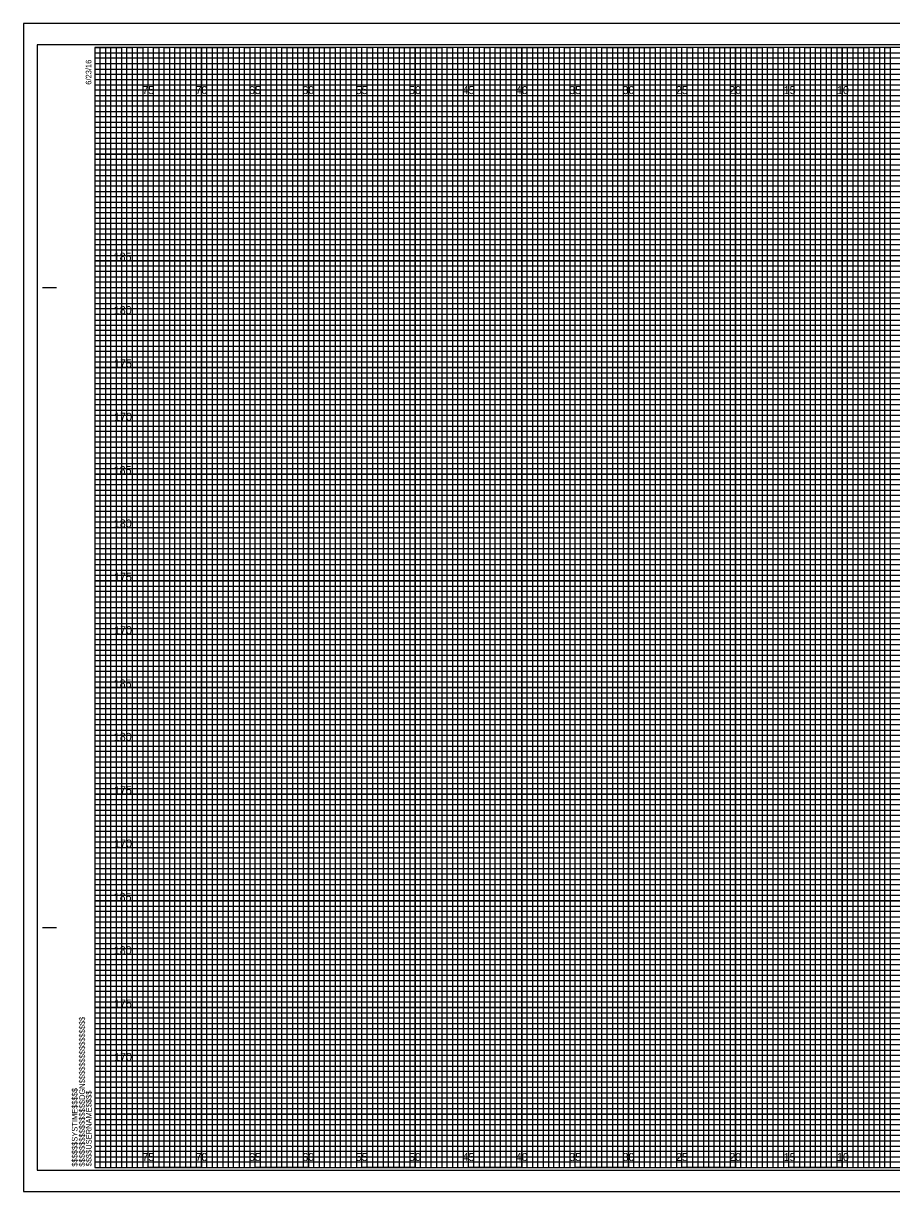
# Model space of a CAD drawing. Extents: x -7 to 162, y -2 to 767.
# Drawn here: x -6.7 to 74.6, y 217.8 to 327.2 of the extents above; entities that cross this region are included whole.
import ezdxf

# ---------------------------------------------------------------- set-up
doc = ezdxf.new("R2010")
doc.units = 0
for name, color, linetype in [('Exist Cross Section Cell', 7, 'Continuous'), ('Prop CMT Pvmt Course 1', 7, 'Continuous'), ('Prop CMT Pvmt Course 1 Wedge', 7, 'Continuous'), ('Prop CMT Pvmt Course 2', 7, 'Continuous'), ('Prop CMT Pvmt Course 3', 7, 'Continuous'), ('Prop CMT Pvmt Surface Shoulder', 7, 'Continuous'), ('Prop CMT Shld Paved Course 2', 7, 'Continuous'), ('Prop CMT Shld Paved Course 3', 7, 'Continuous'), ('Prop CMT Slope Grass', 7, 'Continuous'), ('Prop CMT Subgrade Earthwork', 7, 'Continuous'), ('Scratch_Level_0', 7, 'Continuous')]:
    doc.layers.add(name, color=color, linetype=linetype)

msp = doc.modelspace()

# ---------------------------------------------------------------- linework, layer by layer
at = {"layer": 'Prop CMT Pvmt Course 1'}
for p, q in [((0, 324.5), (130, 324.5)), ((130, 323.99), (0, 323.99)), ((0, 323.99), (0, 323.5)), ((0, 323.5), (130, 323.5)), ((130, 322.94), (0, 322.94)), ((0, 322.94), (0, 322)), ((0, 322), (160, 322))]:
    msp.add_line(p, q, dxfattribs=at)
for points in [[(0, 321.5), (135, 321.5), (160, 321.5), (160, 321), (0, 321)], [(0, 320.5), (160, 320.5), (160, 319.5), (0, 319.5)], [(0, 319), (160, 319), (160, 318.5), (0, 318.49)], [(0, 318), (160, 318), (160, 317), (0, 317)], [(0, 316.5), (160, 316.5), (160, 316), (0, 316)], [(0, 315.5), (160, 315.5), (160, 314.5), (0, 314.5)], [(0, 314), (160, 314), (160, 313.5), (0, 313.5)], [(0, 313), (160, 313), (160, 312), (0, 312)], [(0, 311.5), (160, 311.5), (160, 311), (0, 311)], [(0, 310.5), (160, 310.5), (160, 309.5), (0, 309.5)], [(0, 309), (160, 309), (160, 308.5), (0, 308.5)], [(0, 308), (160, 308), (160, 306.98), (160, 306.5), (160, 306), (0, 306)], [(0, 307), (160, 307), (160, 306.5), (0, 306.5)], [(0, 305.5), (160, 305.5), (160, 304.5), (0, 304.51)], [(0, 304.51), (160, 304.5), (160, 304), (0, 304)], [(0, 303.5), (160, 303.5), (160, 303), (0, 303)], [(0, 302), (160, 302), (160, 301.5), (0, 301.5)], [(0, 301), (160, 301), (160, 300.5), (0, 300.5)], [(-0.04, 299.44), (160, 299.44), (160, 298.94), (-0.04, 298.94)], [(0, 298.5), (160, 298.5), (160, 298), (0, 298)], [(0, 297), (160, 297), (160, 296.5), (0, 296.5)], [(0, 296), (160, 296), (160, 295.5), (0, 295.5)], [(0, 294.5), (160, 294.5), (160, 294), (0, 294)], [(0, 293.5), (160, 293.5), (160, 293), (0, 293)], [(0, 292), (160, 292), (160, 291.5), (0, 291.5)], [(0, 291), (160, 291), (160, 290.5), (0, 290.5)], [(0, 289.5), (160, 289.5), (160, 288.99), (0, 289)], [(0, 288.5), (160, 288.5), (160, 288), (0, 288)], [(0, 287), (160, 287), (160, 286.5), (0, 286.5)], [(0, 286), (160, 286), (160, 285.5), (0, 285.5)], [(0, 284.5), (160, 284.5), (160, 284), (0, 284)], [(0, 283.5), (160, 283.5), (160, 283), (0, 283)], [(0, 282), (160, 282), (160, 281.5), (0, 281.5)], [(0, 281), (160, 281), (160, 280.5), (0, 280.5)], [(0, 279.5), (160, 279.5), (160, 279), (0, 279)], [(0, 278.5), (160.03, 278.45), (160, 278), (0, 278)], [(0, 277), (160, 277), (160, 276.5), (0, 276.5)], [(0, 276), (160, 276), (160, 275.5), (0, 275.5)], [(0, 274.5), (160, 274.5), (160, 274), (0, 274)], [(0, 273.5), (160, 273.5), (160, 273), (0, 273)], [(0, 272), (160, 272), (160, 271.5), (0, 271.5)], [(0, 271), (160, 271), (160, 270.5), (0, 270.5)], [(0, 269.5), (160, 269.5), (160, 269), (0, 269)], [(0, 268.5), (160, 268.5), (160, 268), (0, 268)], [(0, 267), (160, 267), (160, 266.5), (0, 266.5)], [(0, 266), (160, 266), (160, 265.5), (0, 265.5)], [(0, 264.5), (160, 264.5), (160, 264), (0, 264)], [(0, 263.5), (160, 263.5), (160, 263), (0, 263)], [(0, 262), (160, 262), (160, 261.5), (0, 261.5)], [(0, 261), (160, 261), (160, 260.5), (0, 260.5)], [(0, 259.5), (160, 259.5), (160, 258.99), (0, 259)], [(0, 258.5), (160, 258.5), (160, 258), (0, 258)], [(0, 257), (160, 257), (160, 256.5), (0, 256.5)], [(0, 256), (160, 256), (160, 255.5), (0, 255.5)], [(0, 254.5), (160, 254.5), (160, 254), (0, 254)], [(0, 253.5), (160, 253.5), (160, 253), (0, 253)], [(0, 252), (160, 252), (160, 251.5), (0, 251.5)], [(0, 251), (160, 251), (160, 250.5), (0, 250.5)], [(0, 249.5), (160, 249.5), (160, 249), (0, 249)], [(0, 248.5), (160.03, 248.46), (160, 248), (0, 248)], [(0, 247), (160, 247), (160, 246.5), (0, 246.5)], [(0, 246), (160, 246), (160, 245.5), (0, 245.5)], [(0, 244.5), (160, 244.5), (160, 244), (0, 244)], [(0, 243.5), (160, 243.5), (160, 243), (0, 243)], [(0, 242), (160, 242), (160, 241.5), (0, 241.5)], [(0, 241), (160, 241), (160, 240.5), (0, 240.5)], [(0, 239.5), (160, 239.5), (160, 239), (0, 239)], [(0, 238.5), (160, 238.5), (160, 238), (0, 238)], [(0, 237), (160, 237), (160, 236.5), (0, 236.5)], [(0, 236), (160, 236), (160, 235.5), (0, 235.5)], [(0, 234.5), (160, 234.5), (160, 234), (0, 234)], [(0, 233.5), (160, 233.5), (160, 233), (0, 233)], [(0, 232), (160, 232), (160, 231.5), (0, 231.5)], [(0, 231), (160, 231), (160, 230.5), (0, 230.5)], [(0, 229.5), (160, 229.5), (160, 229), (0, 229)], [(0, 228.5), (160, 228.5), (160, 228), (0, 228)], [(0, 227), (160, 227), (160, 226.5), (0, 226.5)], [(0, 226), (160, 226), (160, 225.5), (0, 225.5)], [(0, 224.5), (160, 224.5), (160, 224), (0, 224)], [(0, 223.5), (160, 223.5), (160, 223), (0, 223)], [(0, 222), (160, 222), (160, 221.5), (0, 221.5)], [(0, 221), (160, 221), (160, 220.5), (0, 220.5)]]:
    msp.add_lwpolyline(points, dxfattribs=at)
at = {"layer": 'Prop CMT Pvmt Course 2'}
for p, q in [((5, 220), (5, 325)), ((10, 220), (10, 325)), ((15, 220), (15, 325)), ((20, 220), (20, 325)), ((25, 220), (25, 325)), ((30, 220), (30, 325)), ((35, 220), (35, 325)), ((40, 220), (40, 325)), ((45, 220), (45, 325)), ((50, 220), (50, 325)), ((55, 220), (55, 325)), ((60, 220), (60, 325)), ((65, 220), (65, 325)), ((70, 220), (70, 325)), ((0, 320), (160, 320)), ((0, 315), (160, 315)), ((0, 310), (160, 310)), ((0, 305), (160, 305)), ((0, 300), (160, 300)), ((0, 295), (160, 295)), ((0, 290), (160, 290)), ((0, 285), (160, 285)), ((0, 280), (160, 280)), ((0, 275), (160, 275)), ((0, 270), (160, 270)), ((0, 265), (160, 265)), ((0, 260), (160, 260)), ((0, 255), (160, 255)), ((0, 250), (160, 250)), ((0, 245), (160, 245)), ((0, 240), (160, 240)), ((0, 235), (160, 235)), ((0, 230), (160, 230)), ((0, 225), (160, 225))]:
    msp.add_line(p, q, dxfattribs=at)
at = {"layer": 'Prop CMT Pvmt Course 3'}
for p, q in [((161.65, 327.25), (-6.7, 327.25)), ((-6.7, 327.25), (-6.7, 217.75)), ((-6.7, 217.75), (161.65, 217.75))]:
    msp.add_line(p, q, dxfattribs=at)
at = {"layer": 'Prop CMT Pvmt Surface Shoulder'}
for points in [[(0, 325), (2.5, 325), (2.5, 220), (7.5, 220), (7.5, 325), (12.5, 325), (12.5, 220), (17.5, 220), (17.5, 325), (22.5, 325), (22.5, 220), (27.5, 220), (27.5, 325), (32.5, 325), (32.5, 220), (37.5, 220), (37.5, 325), (42.5, 325), (42.5, 220), (47.5, 220), (47.5, 325), (52.5, 325), (52.5, 220), (57.5, 220), (57.5, 325), (62.5, 325), (62.5, 220), (67.5, 220), (67.5, 325), (72.5, 325), (72.5, 220), (77.5, 220)], [(0, 322.5), (137.5, 322.5)], [(0, 312.5), (160, 312.5), (160, 317.5), (0, 317.5)], [(0, 302.5), (160, 302.5), (160, 307.5), (0, 307.5)], [(0, 292.5), (160, 292.5), (160, 297.5), (0, 297.5)], [(0, 282.5), (160, 282.5), (160, 287.5), (0, 287.5)], [(0, 272.5), (160, 272.5), (160, 277.5), (0, 277.5)], [(0, 262.5), (160, 262.5), (160, 267.5), (0, 267.5)], [(0, 252.5), (160, 252.5), (160, 257.5), (0, 257.5)], [(0, 242.5), (160, 242.5), (160, 247.5), (0, 247.5)], [(0, 232.5), (160, 232.5), (160, 237.5), (0, 237.5)], [(0, 222.5), (160, 222.5), (160, 227.5), (0, 227.5)]]:
    msp.add_lwpolyline(points, dxfattribs=at)
at = {"layer": 'Prop CMT Shld Paved Course 2'}
msp.add_lwpolyline([(-6.7, 217.75), (161.65, 217.75), (161.65, 327.25), (-6.7, 327.25)], close=True, dxfattribs=at)
at = {"layer": 'Prop CMT Shld Paved Course 3'}
msp.add_lwpolyline([(-5.4, 219.75), (161.2, 219.75), (161.2, 325.25), (-5.4, 325.25)], close=True, dxfattribs=at)
at = {"layer": 'Prop CMT Slope Grass'}
for points in [[(0, 220), (0.5, 220), (0.5, 325), (1, 325), (1, 220)], [(1, 220), (1.5, 220), (1.5, 325), (2, 325), (2, 220)], [(2.5, 220), (3, 220), (3, 325), (3.5, 325), (3.5, 220)], [(3.5, 220), (4, 220), (4, 325), (4.5, 325), (4.5, 220)], [(5, 220), (5.5, 220), (5.5, 325), (6, 325), (6, 220)], [(6, 220), (6.5, 220), (6.5, 325), (7, 325), (7, 220)], [(7.5, 220), (8, 220), (8, 325), (8.5, 325), (8.5, 220)], [(8.5, 220), (9, 220), (9, 325), (9.5, 325), (9.5, 220)], [(10, 220), (10.5, 220), (10.5, 325), (11, 325), (11, 220)], [(11, 220), (11.5, 220), (11.5, 325), (12, 325), (12, 220)], [(12.5, 220), (13, 220), (13, 325), (13.5, 325), (13.5, 220)], [(13.5, 220), (14, 220), (14, 325), (14.5, 325), (14.5, 220)], [(15, 220), (15.5, 220), (15.5, 325), (16, 325), (16, 220)], [(16, 220), (16.5, 220), (16.5, 325), (17, 325), (17, 220)], [(17.5, 220), (18, 220), (18, 325), (18.5, 325), (18.5, 220)], [(18.5, 220), (19, 220), (19, 325), (19.5, 325), (19.5, 220)], [(20, 220), (20.5, 220), (20.5, 325), (21, 325), (21, 220)], [(21, 220), (21.5, 220), (21.5, 325), (22, 325), (22, 220)], [(22.5, 220), (23, 220), (23, 325), (23.5, 325), (23.5, 220)], [(23.5, 220), (24, 220), (24, 325), (24.5, 325), (24.5, 220)], [(25, 220), (25.5, 220), (25.5, 325), (26, 325), (26, 220)], [(26, 220), (26.5, 220), (26.5, 325), (27, 325), (27, 220)], [(27.5, 220), (28, 220), (28, 325), (28.5, 325), (28.5, 220)], [(28.5, 220), (29, 220), (29, 325), (29.5, 325), (29.5, 220)], [(30, 220), (30.5, 220), (30.5, 325), (31, 325), (31, 220)], [(31, 220), (31.5, 220), (31.5, 325), (32, 325), (32, 220)], [(32.5, 220), (33, 220), (33, 325), (33.5, 325), (33.5, 220)], [(33.5, 220), (34, 220), (34, 325), (34.5, 325), (34.5, 220)], [(35, 220), (35.5, 220), (35.5, 325), (36, 325), (36, 220)], [(36, 220), (36.5, 220), (36.5, 325), (37, 325), (37, 220)], [(37.5, 220), (38, 220), (38, 325), (38.5, 325), (38.5, 220)], [(38.5, 220), (39, 220), (39, 325), (39.5, 325), (39.5, 220)], [(40, 220), (40.5, 220), (40.5, 325), (41, 325), (41, 220)], [(41, 220), (41.5, 220), (41.5, 325), (42, 325), (42, 220)], [(42.5, 220), (43, 220), (43, 325), (43.5, 325), (43.5, 220)], [(43.5, 220), (44, 220), (44, 325), (44.5, 325), (44.5, 220)], [(45, 220), (45.5, 220), (45.5, 325), (46, 325), (46, 220)], [(46, 220), (46.5, 220), (46.5, 325), (47, 325), (47, 220)], [(47.5, 220), (48, 220), (48, 325), (48.5, 325), (48.5, 220)], [(48.5, 220), (49, 220), (49, 325), (49.5, 325), (49.5, 220)], [(50, 220), (50.5, 220), (50.5, 325), (51, 325), (51, 220)], [(51, 220), (51.5, 220), (51.5, 325), (52, 325), (52, 220)], [(52.5, 220), (53, 220), (53, 325), (53.5, 325), (53.5, 220)], [(53.5, 220), (54, 220), (54, 325), (54.5, 325), (54.5, 220)], [(55, 220), (55.5, 220), (55.5, 325), (56, 325), (56, 220)], [(56, 220), (56.5, 220), (56.5, 325), (57, 325), (57, 220)], [(57.5, 220), (58, 220), (58, 325), (58.5, 325), (58.5, 220)], [(58.5, 220), (59, 220), (59, 325), (59.5, 325), (59.5, 220)], [(60, 220), (60.5, 220), (60.5, 325), (61, 325), (61, 220)], [(61, 220), (61.5, 220), (61.5, 325), (62, 325), (62, 220)], [(62.5, 220), (63, 220), (63, 325), (63.5, 325), (63.5, 220)], [(63.5, 220), (64, 220), (64, 325), (64.5, 325), (64.5, 220)], [(65, 220), (65.5, 220), (65.5, 325), (66, 325), (66, 220)], [(66, 220), (66.5, 220), (66.5, 325), (67, 325), (67, 220)], [(67.5, 220), (68, 220), (68, 325), (68.5, 325), (68.5, 220)], [(68.5, 220), (69, 220), (69, 325), (69.5, 325), (69.5, 220)], [(70, 220), (70.5, 220), (70.5, 325), (71, 325), (71, 220)], [(71, 220), (71.5, 220), (71.5, 325), (72, 325), (72, 220)], [(72.5, 220), (73, 220), (73, 325), (73.5, 325), (73.5, 220)], [(73.5, 220), (74, 220), (74, 325), (74.5, 325), (74.5, 220)]]:
    msp.add_lwpolyline(points, dxfattribs=at)
at = {"layer": 'Prop CMT Subgrade Earthwork'}
for p, q in [((-4.9, 302.5), (-3.65, 302.5)), ((-4.85, 302.5), (-3.6, 302.5)), ((-4.9, 242.5), (-3.65, 242.5)), ((-4.85, 242.5), (-3.6, 242.5)), ((0, 220), (0, 220)), ((0, 220), (0, 220)), ((0, 220), (0, 220)), ((0, 220), (0, 220)), ((0, 220), (0, 220)), ((0, 220), (0, 220)), ((0, 220), (0, 220))]:
    msp.add_line(p, q, dxfattribs=at)
msp.add_lwpolyline([(160, 325), (0, 325), (0, 220), (160, 220)], close=True, dxfattribs=at)
at = {"layer": 'Scratch_Level_0'}
for p, q in [((5, 325), (0, 325)), ((5, 220), (5, 325)), ((15, 325), (10, 325)), ((10, 325), (10, 220)), ((15, 220), (15, 325)), ((25, 325), (20, 325)), ((20, 325), (20, 220)), ((25, 220), (25, 325)), ((35, 325), (30, 325)), ((30, 325), (30, 220)), ((35, 220), (35, 325)), ((45, 325), (40, 325)), ((40, 325), (40, 220)), ((45, 220), (45, 325)), ((55, 325), (50, 325)), ((50, 325), (50, 220)), ((55, 220), (55, 325)), ((65, 325), (60, 325)), ((60, 325), (60, 220)), ((65, 220), (65, 325)), ((75, 325), (70, 325)), ((70, 325), (70, 220)), ((10, 220), (5, 220)), ((20, 220), (15, 220)), ((30, 220), (25, 220)), ((40, 220), (35, 220)), ((50, 220), (45, 220)), ((60, 220), (55, 220)), ((70, 220), (65, 220))]:
    msp.add_line(p, q, dxfattribs=at)
for points in [[(0, 320), (160, 320), (160, 315), (0, 315)], [(0, 310), (160, 310), (160, 305), (0, 305)], [(0, 300), (160, 300), (160, 295), (0, 295)], [(0, 290), (160, 290), (160, 285), (0, 285)], [(0, 280), (160, 280), (160, 275), (0, 275)], [(0, 270), (160, 270), (160, 265), (0, 265)], [(0, 260), (160, 260), (160, 255), (0, 255)], [(0, 250), (160, 250), (160, 245), (0, 245)], [(0, 240), (160, 240), (160, 235), (0, 235)], [(0, 230), (160, 230), (160, 225), (0, 225)]]:
    msp.add_lwpolyline(points, dxfattribs=at)

# ---------------------------------------------------------------- texts
at = {"layer": 'Exist Cross Section Cell'}
for s, p in [('75', (4.44, 320.62)), ('70', (9.43, 320.62)), ('65', (14.44, 320.62)), ('60', (19.43, 320.62)), ('55', (24.44, 320.62)), ('50', (29.43, 320.62)), ('45', (34.44, 320.62)), ('40', (39.43, 320.62)), ('35', (44.44, 320.62)), ('30', (49.43, 320.62)), ('25', (54.44, 320.62)), ('20', (59.43, 320.62)), ('15', (64.53, 320.62)), ('10', (69.52, 320.62)), ('75', (4.44, 220.62)), ('70', (9.43, 220.62)), ('65', (14.44, 220.62)), ('60', (19.43, 220.62)), ('55', (24.44, 220.62)), ('50', (29.43, 220.62)), ('45', (34.44, 220.62)), ('40', (39.43, 220.62)), ('35', (44.44, 220.62)), ('30', (49.43, 220.62)), ('25', (54.44, 220.62)), ('20', (59.43, 220.62)), ('15', (64.53, 220.62)), ('10', (69.52, 220.62))]:
    msp.add_text(s, height=0.75, dxfattribs=at).set_placement(p)
at = {"layer": 'Prop CMT Pvmt Course 1 Wedge'}
for s, p in [('185', (1.76, 305)), ('180', (1.77, 300)), ('175', (1.79, 295)), ('170', (1.8, 290)), ('185', (1.76, 285)), ('180', (1.77, 280)), ('175', (1.79, 275)), ('170', (1.8, 270)), ('185', (1.76, 265)), ('180', (1.77, 260)), ('175', (1.79, 255)), ('170', (1.8, 250)), ('185', (1.76, 245)), ('180', (1.77, 240)), ('175', (1.79, 235)), ('170', (1.8, 230))]:
    msp.add_text(s, height=0.75, dxfattribs=at).set_placement(p)
at = {"layer": 'Prop CMT Subgrade Earthwork'}
for s, p in [('6/23/16', (-0.33, 321.5)), ('$$$$$$$$$$$$$$$$DGN$$$$$$$$$$$$$$$$', (-0.94, 220.09)), ('$$$$$$SYSTIME$$$$$', (-1.63, 220.09)), ('$$$$USERNAME$$$$', (-0.31, 220.12))]:
    msp.add_text(s, height=0.525, rotation=90, dxfattribs=at).set_placement(p)

doc.saveas('drawing.dxf')
